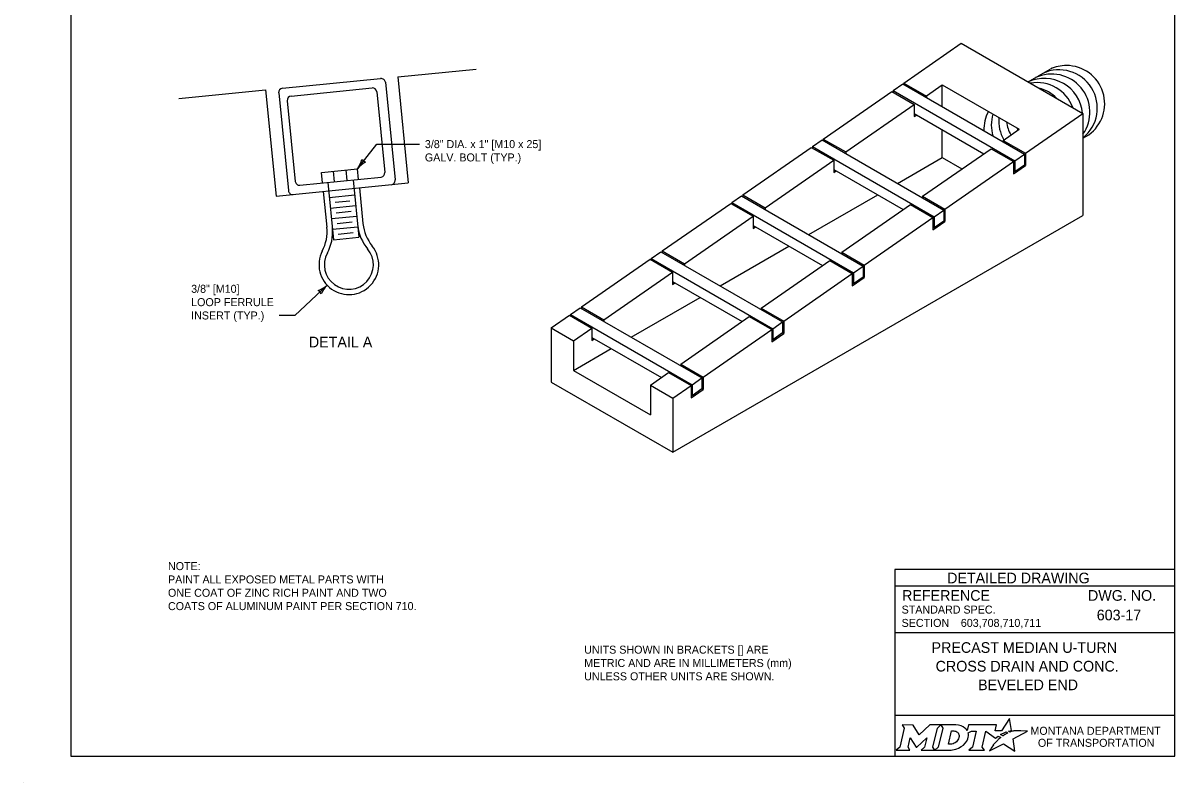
# Model space of a CAD drawing. Extents: x 49991.4 to 50021, y 49987.6 to 50011.4.
# Drawn here: x 49999.98 to 50008.61, y 49999.86 to 50005.56 of the extents above; entities that cross this region are included whole.
import ezdxf

# ---------------------------------------------------------------- set-up
doc = ezdxf.new("R2010")
doc.units = 0
for name, color, linetype in [('Level 1', 7, 'Continuous'), ('Level 2', 7, 'Continuous'), ('Level 3', 7, 'Continuous')]:
    doc.layers.add(name, color=color, linetype=linetype)

msp = doc.modelspace()

# ---------------------------------------------------------------- linework, layer by layer
at = {"layer": 'Level 1'}
for p, q in [((50006.5822, 50005.1123), (50007.0126, 50005.4112)), ((50007.0126, 50005.4112), (50007.9246, 50004.8846)), ((50002.7863, 50005.1589), (50003.3735, 50005.2173)), ((50007.5144, 50005.1214), (50007.68, 50005.217)), ((50001.9223, 50005.0733), (50002.6583, 50005.1461)), ((50002.7863, 50005.1589), (50002.8654, 50004.3629)), ((50001.1447, 50004.9957), (50001.7943, 50005.0605)), ((50001.7943, 50005.0605), (50001.8735, 50004.2637)), ((50001.8935, 50005.0381), (50001.9663, 50004.3052)), ((50001.9863, 50005.0149), (50002.5943, 50005.0757)), ((50002.6295, 50005.0469), (50002.6895, 50004.4421)), ((50002.6935, 50005.1181), (50002.7662, 50004.3854)), ((50005.9776, 50004.6924), (50006.492, 50005.0497)), ((50006.492, 50005.0497), (50006.66, 50004.9527)), ((50006.5008, 50005.0557), (50006.5734, 50005.1062)), ((50006.5008, 50005.0557), (50007.4128, 50004.5292)), ((50006.5008, 50005.0557), (50006.5008, 50005.0446)), ((50006.5734, 50005.1062), (50007.4854, 50004.5796)), ((50006.5822, 50005.1123), (50006.7502, 50005.0152)), ((50006.5822, 50005.1123), (50006.5822, 50005.1011)), ((50006.7502, 50005.0153), (50006.8699, 50005.0984)), ((50006.8699, 50005.0984), (50007.4459, 50004.7658)), ((50006.8699, 50004.935), (50006.8699, 50005.0984)), ((50001.9575, 50004.9797), (50002.0175, 50004.375)), ((50006.1456, 50004.5954), (50006.66, 50004.9527)), ((50006.66, 50004.9527), (50006.66, 50004.861)), ((50006.7502, 50005.0152), (50006.7502, 50005.0041)), ((50006.66, 50004.8838), (50007.1819, 50004.5825)), ((50006.66, 50004.861), (50006.6779, 50004.8734)), ((50007.4942, 50004.5857), (50007.9246, 50004.8846)), ((50007.9246, 50004.8846), (50007.9246, 50004.1182)), ((50005.9776, 50004.6924), (50006.1456, 50004.5955)), ((50005.9776, 50004.6924), (50005.9776, 50004.6813)), ((50006.8699, 50004.5532), (50006.8699, 50004.7626)), ((50007.3262, 50004.6827), (50007.4459, 50004.7658)), ((50007.9246, 50004.6991), (50007.9675, 50004.7238)), ((50005.3731, 50004.2727), (50005.8876, 50004.63)), ((50005.8876, 50004.63), (50006.0555, 50004.5329)), ((50005.8962, 50004.636), (50005.9688, 50004.6864)), ((50005.8962, 50004.636), (50006.8082, 50004.1094)), ((50005.8962, 50004.636), (50005.8962, 50004.625)), ((50005.9688, 50004.6864), (50006.8808, 50004.1599)), ((50006.7216, 50004.2629), (50007.236, 50004.6201)), ((50007.236, 50004.6201), (50007.404, 50004.5232)), ((50007.3262, 50004.6827), (50007.4942, 50004.5857)), ((50007.3262, 50004.6827), (50007.3262, 50004.6715)), ((50005.5411, 50004.1756), (50006.0555, 50004.5329)), ((50006.0555, 50004.5329), (50006.0555, 50004.4412)), ((50006.1456, 50004.5955), (50006.1456, 50004.5843)), ((50006.5348, 50004.3596), (50006.8699, 50004.5532)), ((50006.8699, 50004.5532), (50007.0171, 50004.4681)), ((50006.8896, 50004.166), (50007.404, 50004.5232)), ((50007.404, 50004.5232), (50007.404, 50004.4315)), ((50007.4128, 50004.5292), (50007.4854, 50004.5796)), ((50007.4128, 50004.5292), (50007.4128, 50004.4492)), ((50007.4854, 50004.5796), (50007.4854, 50004.4996)), ((50007.4942, 50004.5857), (50007.4942, 50004.494)), ((50002.214, 50004.4426), (50002.4847, 50004.4697)), ((50002.222, 50004.363), (50002.214, 50004.4426)), ((50002.3016, 50004.4514), (50002.3095, 50004.3718)), ((50002.397, 50004.4609), (50002.405, 50004.3813)), ((50002.4927, 50004.3901), (50002.4847, 50004.4697)), ((50006.0555, 50004.464), (50006.5774, 50004.1628)), ((50006.0555, 50004.4412), (50006.0734, 50004.4537)), ((50007.404, 50004.4315), (50007.4942, 50004.494)), ((50007.404, 50004.4543), (50007.4128, 50004.4492)), ((50007.4128, 50004.4492), (50007.4854, 50004.4996)), ((50007.4854, 50004.4996), (50007.4942, 50004.494)), ((50001.8735, 50004.2637), (50002.8654, 50004.3629)), ((50002.0527, 50004.3461), (50002.6615, 50004.407)), ((50002.2617, 50004.367), (50002.3047, 50003.9362)), ((50002.4528, 50004.3861), (50002.4958, 50003.9552)), ((50002.2283, 50004.2992), (50002.2551, 50004.0313)), ((50002.2729, 50004.2546), (50002.464, 50004.2736)), ((50002.499, 50004.3263), (50002.5258, 50004.0581)), ((50005.2916, 50004.2162), (50005.3643, 50004.2666)), ((50005.3643, 50004.2666), (50006.2763, 50003.7401)), ((50005.3731, 50004.2727), (50005.5411, 50004.1756)), ((50005.3731, 50004.2727), (50005.3731, 50004.2615)), ((50005.8689, 50003.9753), (50006.3855, 50004.2735)), ((50006.7216, 50004.2629), (50006.8896, 50004.166)), ((50006.7216, 50004.2629), (50006.7216, 50004.2518)), ((50002.2809, 50004.175), (50002.472, 50004.194)), ((50002.3167, 50004.2187), (50002.4282, 50004.2298)), ((50004.7685, 50003.8528), (50005.283, 50004.2101)), ((50005.283, 50004.2101), (50005.451, 50004.1132)), ((50005.2916, 50004.2162), (50006.2036, 50003.6896)), ((50005.2916, 50004.2162), (50005.2916, 50004.2051)), ((50005.5411, 50004.1756), (50005.5411, 50004.1645)), ((50006.1171, 50003.8432), (50006.6315, 50004.2004)), ((50006.6315, 50004.2004), (50006.7995, 50004.1033)), ((50002.2888, 50004.0954), (50002.4799, 50004.1144)), ((50002.3247, 50004.1391), (50002.4362, 50004.1502)), ((50004.8493, 50002.3427), (50007.9246, 50004.1182)), ((50004.9365, 50003.7558), (50005.4511, 50004.1131)), ((50005.451, 50004.1132), (50005.451, 50004.0214)), ((50006.2851, 50003.7461), (50006.7995, 50004.1033)), ((50006.7995, 50004.1033), (50006.7995, 50004.0117)), ((50006.8082, 50004.1094), (50006.8808, 50004.1599)), ((50006.8082, 50004.1094), (50006.8082, 50004.0294)), ((50006.8808, 50004.1599), (50006.8808, 50004.0799)), ((50006.8896, 50004.166), (50006.8896, 50004.0742)), ((50002.2968, 50004.0158), (50002.4879, 50004.0348)), ((50002.3326, 50004.0595), (50002.4442, 50004.0706)), ((50005.451, 50004.0442), (50005.9728, 50003.743)), ((50005.451, 50004.0214), (50005.4689, 50004.0339)), ((50006.7995, 50004.0117), (50006.8896, 50004.0742)), ((50006.7995, 50004.0345), (50006.8082, 50004.0294)), ((50006.8082, 50004.0294), (50006.8808, 50004.0799)), ((50006.8808, 50004.0799), (50006.8896, 50004.0742)), ((50002.3047, 50003.9362), (50002.4958, 50003.9552)), ((50002.3406, 50003.9799), (50002.4521, 50003.991)), ((50004.6872, 50003.7964), (50004.7598, 50003.8468)), ((50004.7598, 50003.8468), (50005.6718, 50003.3203)), ((50004.7685, 50003.8528), (50004.9365, 50003.7559)), ((50004.7685, 50003.8528), (50004.7685, 50003.8418)), ((50005.2032, 50003.5908), (50005.7197, 50003.8891)), ((50006.1171, 50003.8432), (50006.2851, 50003.7461)), ((50006.1171, 50003.8432), (50006.1171, 50003.832)), ((50004.164, 50003.4331), (50004.6784, 50003.7904)), ((50004.6784, 50003.7904), (50004.8464, 50003.6933)), ((50004.6872, 50003.7964), (50005.5992, 50003.2698)), ((50004.6872, 50003.7964), (50004.6872, 50003.7853)), ((50004.9365, 50003.7559), (50004.9365, 50003.7448)), ((50005.5125, 50003.4233), (50006.027, 50003.7806)), ((50006.027, 50003.7806), (50006.195, 50003.6836)), ((50006.2851, 50003.7461), (50006.2851, 50003.6544)), ((50004.332, 50003.336), (50004.8465, 50003.6933)), ((50004.8464, 50003.6933), (50004.8464, 50003.6016)), ((50005.6805, 50003.3264), (50006.195, 50003.6836)), ((50006.195, 50003.6836), (50006.195, 50003.5919)), ((50006.195, 50003.5919), (50006.2851, 50003.6544)), ((50006.2036, 50003.6896), (50006.2763, 50003.7401)), ((50006.2036, 50003.6896), (50006.2036, 50003.6096)), ((50006.2036, 50003.6096), (50006.2763, 50003.6601)), ((50006.2763, 50003.7401), (50006.2763, 50003.6601)), ((50006.2763, 50003.6601), (50006.2851, 50003.6544)), ((50004.8464, 50003.6244), (50005.3683, 50003.3232)), ((50004.8464, 50003.6016), (50004.8644, 50003.614)), ((50006.195, 50003.6147), (50006.2036, 50003.6096)), ((50004.5373, 50003.2064), (50005.0539, 50003.5046)), ((50004.0826, 50003.3766), (50004.1552, 50003.427)), ((50004.1552, 50003.427), (50005.0672, 50002.9004)), ((50004.164, 50003.4331), (50004.332, 50003.336)), ((50004.164, 50003.4331), (50004.164, 50003.4219)), ((50005.5125, 50003.4233), (50005.6805, 50003.3264)), ((50005.5125, 50003.4233), (50005.5125, 50003.4123)), ((50003.9374, 50003.2757), (50004.0739, 50003.3705)), ((50004.0739, 50003.3705), (50004.2419, 50003.2736)), ((50004.0826, 50003.3766), (50004.9946, 50002.85)), ((50004.0826, 50003.3766), (50004.0826, 50003.3655)), ((50004.332, 50003.336), (50004.332, 50003.3249)), ((50004.908, 50003.0035), (50005.4224, 50003.3608)), ((50005.4224, 50003.3608), (50005.5904, 50003.2638)), ((50005.5992, 50003.2698), (50005.6718, 50003.3203)), ((50005.6718, 50003.3203), (50005.6718, 50003.2403)), ((50005.6805, 50003.3264), (50005.6805, 50003.2346)), ((50003.9374, 50003.2757), (50003.9374, 50002.8692)), ((50003.9374, 50003.2757), (50004.1054, 50003.1788)), ((50004.1054, 50003.1788), (50004.2419, 50003.2736)), ((50004.2419, 50003.2736), (50004.2419, 50003.1818)), ((50005.076, 50002.9065), (50005.5904, 50003.2638)), ((50005.5904, 50003.2638), (50005.5904, 50003.1721)), ((50005.5904, 50003.1721), (50005.6805, 50003.2346)), ((50005.5992, 50003.2698), (50005.5992, 50003.1898)), ((50005.5992, 50003.1898), (50005.6718, 50003.2403)), ((50005.6718, 50003.2403), (50005.6805, 50003.2346)), ((50004.1054, 50003.1788), (50004.1054, 50002.9571)), ((50004.2419, 50003.2046), (50004.7637, 50002.9033)), ((50004.2419, 50003.1818), (50004.2598, 50003.1943)), ((50005.5904, 50003.1948), (50005.5992, 50003.1898)), ((50004.1054, 50002.9571), (50004.3879, 50003.1203)), ((50004.908, 50003.0035), (50005.076, 50002.9065)), ((50004.908, 50003.0035), (50004.908, 50002.9923)), ((50004.1054, 50002.9571), (50004.6814, 50002.6244)), ((50004.6814, 50002.8461), (50004.8179, 50002.941)), ((50004.8179, 50002.941), (50004.9859, 50002.844)), ((50004.9946, 50002.85), (50005.0672, 50002.9004)), ((50005.0672, 50002.9004), (50005.0672, 50002.8204)), ((50005.076, 50002.9065), (50005.076, 50002.8148)), ((50003.9374, 50002.8692), (50004.8493, 50002.3427)), ((50004.6814, 50002.8461), (50004.6814, 50002.6244)), ((50004.6814, 50002.8461), (50004.8493, 50002.7492)), ((50004.8493, 50002.7492), (50004.9859, 50002.844)), ((50004.9859, 50002.844), (50004.9859, 50002.7523)), ((50004.9859, 50002.7523), (50005.076, 50002.8148)), ((50004.9946, 50002.85), (50004.9946, 50002.77)), ((50004.9946, 50002.77), (50005.0672, 50002.8204)), ((50005.0672, 50002.8204), (50005.076, 50002.8148)), ((50004.8493, 50002.7492), (50004.8493, 50002.3427)), ((50004.9859, 50002.7751), (50004.9946, 50002.77)), ((49999.9766, 49999.8624), (49999.9766, 49999.8624))]:
    msp.add_line(p, q, dxfattribs=at)
msp.add_lwpolyline([(50008.6146, 50011.2628), (50000.3356, 50011.2628), (50000.3356, 50000.0624), (50008.6146, 50000.0624)], close=True, dxfattribs=at)
for centre, radius, start, end in [((50007.7457, 50004.9253), 0.2866, 308.61517, 115.02076), ((50007.8012, 50004.9573), 0.2866, 90, 115.0077), ((50007.8012, 50004.9573), 0.2866, 305.47033, 90), ((50002.6619, 50005.1145), 0.0318, 6.49935, 96.49935), ((50007.6349, 50004.8613), 0.2866, 5.16764, 114.82672), ((50007.6903, 50004.8933), 0.2866, 324.83171, 114.99908), ((50001.9255, 50005.0413), 0.0322, 95.71059, 185.71059), ((50002.5975, 50005.0437), 0.0322, 5.71059, 95.71059), ((50007.5794, 50004.8293), 0.2866, 20.2966, 99.69807), ((50007.524, 50004.7973), 0.2866, 44.31473, 75.67994), ((50001.9895, 50004.9829), 0.0322, 95.71059, 185.71059), ((50007.4686, 50004.7653), 0.2866, 152.17102, 182.11216), ((50007.524, 50004.7973), 0.2866, 163.37199, 196.46639), ((50007.5794, 50004.8293), 0.2866, 175.12903, 209.95947), ((50007.6349, 50004.8613), 0.2866, 188.17367, 208.891), ((50007.6903, 50004.8933), 0.2866, 204.23698, 207.82048), ((50002.6579, 50004.4385), 0.0317, 276.41991, 6.41991), ((50002.0496, 50004.3782), 0.0322, 185.61323, 275.61323), ((50002.7345, 50004.3819), 0.0319, 276.23179, 6.23179), ((50001.9983, 50004.3085), 0.0322, 185.90037, 275.90037), ((50001.9367, 50003.9994), 0.32, 332.65107, 5.7128), ((50001.9777, 50003.9913), 0.32, 331.33979, 5.71115), ((50002.8056, 50004.0739), 0.32, 185.70908, 220.06575), ((50002.8443, 50004.0899), 0.32, 185.7047, 218.73449), ((50002.4199, 50003.7495), 0.224, 152.65107, 38.73449), ((50002.4199, 50003.7495), 0.184, 151.33859, 40.06575)]:
    msp.add_arc(centre, radius, start, end, dxfattribs=at)
at = {"layer": 'Level 2'}
for p, q in [((50008.6146, 50001.4624), (50006.5146, 50001.4624)), ((50006.5146, 50001.4624), (50006.5146, 50000.0624)), ((50008.6146, 50001.3374), (50006.5146, 50001.3374)), ((50008.2507, 50001.1223), (50008.2507, 50001.1223)), ((50008.6146, 50000.9874), (50006.5146, 50000.9874)), ((50007.0089, 50001.0629), (50007.0089, 50001.0629)), ((50007.5646, 50000.7383), (50007.5646, 50000.7383)), ((50008.6146, 50000.3693), (50006.5146, 50000.3693))]:
    msp.add_line(p, q, dxfattribs=at)
for points in [[(50006.5701, 50000.2974), (50006.5842, 50000.274), (50006.5507, 50000.1307), (50006.525, 50000.1082), (50006.6266, 50000.1082), (50006.6131, 50000.131), (50006.6293, 50000.2011), (50006.673, 50000.1321), (50006.6783, 50000.1321), (50006.7534, 50000.2016), (50006.737, 50000.1305), (50006.7123, 50000.1085), (50006.8139, 50000.1085), (50006.8001, 50000.1318), (50006.8333, 50000.2742)], [(50006.8333, 50000.2742), (50006.8586, 50000.2974), (50006.7762, 50000.2974), (50006.6966, 50000.2244), (50006.6521, 50000.2971), (50006.5701, 50000.2974)], [(50006.9722, 50000.2974), (50006.8586, 50000.2974), (50006.8733, 50000.2745), (50006.8394, 50000.1307), (50006.8139, 50000.1085), (50006.9245, 50000.1085)], [(50007.3771, 50000.2447), (50007.3668, 50000.2503), (50007.3784, 50000.2531), (50007.39, 50000.2551), (50007.3726, 50000.3452), (50007.3131, 50000.2539), (50007.2658, 50000.2532), (50007.2761, 50000.2973), (50007.0669, 50000.2974), (50007.0568, 50000.2549), (50007.051, 50000.2632)], [(50006.9962, 50000.2107), (50006.995, 50000.2026), (50006.9918, 50000.1933), (50006.9876, 50000.1851), (50006.982, 50000.1776), (50006.9755, 50000.1707), (50006.9676, 50000.1644), (50006.9593, 50000.1597), (50006.9502, 50000.1558), (50006.9411, 50000.1535), (50006.9319, 50000.1526), (50006.916, 50000.1526), (50006.9396, 50000.2526), (50006.9556, 50000.2526), (50006.9632, 50000.252), (50006.9708, 50000.2501), (50006.9774, 50000.2471), (50006.9835, 50000.2429), (50006.9883, 50000.2379), (50006.992, 50000.2319), (50006.9947, 50000.2257), (50006.9963, 50000.2183), (50006.9963, 50000.2153), (50006.9962, 50000.2107)], [(50007.0636, 50000.2383), (50007.0882, 50000.2514), (50007.1251, 50000.2514), (50007.0965, 50000.1309), (50007.069, 50000.1082), (50007.1852, 50000.1082), (50007.1682, 50000.1311), (50007.1964, 50000.2513), (50007.2677, 50000.1996), (50007.2888, 50000.2147), (50007.3085, 50000.2038)], [(50007.2527, 50000.1479), (50007.2374, 50000.1235), (50007.2327, 50000.116), (50007.2269, 50000.1074), (50007.2246, 50000.1031), (50007.3299, 50000.1562), (50007.4138, 50000.1011), (50007.4007, 50000.1938), (50007.5076, 50000.2522), (50007.4583, 50000.253), (50007.4282, 50000.2534), (50007.4074, 50000.2537), (50007.4006, 50000.2522), (50007.3957, 50000.251), (50007.3873, 50000.2487), (50007.3771, 50000.2447)], [(50007.3267, 50000.2171), (50007.3243, 50000.2154), (50007.306, 50000.225), (50007.3163, 50000.2307), (50007.3204, 50000.2329), (50007.329, 50000.2369), (50007.3347, 50000.2395), (50007.3426, 50000.2425), (50007.3499, 50000.2452), (50007.3617, 50000.2378), (50007.3577, 50000.2357), (50007.3531, 50000.2332), (50007.3489, 50000.231), (50007.3439, 50000.2281), (50007.342, 50000.227), (50007.3393, 50000.2254), (50007.3368, 50000.224), (50007.3345, 50000.2224), (50007.3319, 50000.2206), (50007.3292, 50000.2188), (50007.3267, 50000.2171)], [(50006.9702, 50000.1158), (50006.9786, 50000.1184), (50006.9916, 50000.1238), (50007.012, 50000.1348)], [(50007.2666, 50000.164), (50007.2666, 50000.164)]]:
    msp.add_lwpolyline(points, dxfattribs=at)
for centre, radius, start, end in [((50006.9953, 50000.219), 0.0709, 339.53292, 15.85821), ((50006.9513, 50000.2363), 0.1183, 300.91025, 339.13831)]:
    msp.add_arc(centre, radius, start, end, dxfattribs=at)
for centre, major_axis, ratio, start_param, end_param in [((50006.9701, 50000.25), (0.0834, -0.0037), 0.568097, 0.61298, 1.570796), ((50007.0257, 50000.2573), (0.0361, -0.0295), 0.469099, 1.225588, 1.570796), ((50007.2974, 50000.1941), (-0.0112, -0.0097), 0.021651, 3.157348, 6.283185), ((50006.9248, 50000.2568), (0, 0.1484), 0.987302, 3.139398, 3.456847), ((50007.2597, 50000.1559), (-0.00694, -0.00806), 0.008222, 0, 3.137361), ((50007.2764, 50000.1742), (-0.0098, -0.0102), 0.016458, 3.141593, 6.279097)]:
    msp.add_ellipse(centre, major_axis=major_axis, ratio=ratio, start_param=start_param, end_param=end_param, dxfattribs=at)
at = {"layer": 'Level 3'}
for p, q in [((50002.4847, 50004.4697), (50002.6287, 50004.6544)), ((50002.6287, 50004.6544), (50002.9499, 50004.6544)), ((50002.2564, 50003.5964), (50002.0137, 50003.369)), ((50002.0137, 50003.369), (50001.8967, 50003.369))]:
    msp.add_line(p, q, dxfattribs=at)
for centre, radius, start, end in [((50002.2941, 50004.6037), 0.233, 324.88581, 344.13566), ((50002.6543, 50004.3259), 0.2223, 119.51451, 139.69802), ((50002.5635, 50004.5708), 0.0548, 214.19732, 249.91968), ((50002.1112, 50003.7648), 0.2223, 290.59191, 310.77541), ((50002.4239, 50003.4345), 0.233, 135.96321, 155.21306), ((50002.1628, 50003.5087), 0.0548, 25.27471, 60.99708)]:
    msp.add_arc(centre, radius, start, end, dxfattribs=at)

# ---------------------------------------------------------------- texts
at = {"layer": 'Level 2'}
for s, height, p in [('3/8" DIA. x 1" [M10 x 25]', 0.06, (50002.9899, 50004.6244)), ('GALV. BOLT (TYP.)', 0.06, (50002.9899, 50004.5244)), ('3/8" [M10] ', 0.06, (50001.2373, 50003.539)), ('LOOP FERRULE', 0.06, (50001.2373, 50003.439)), ('INSERT (TYP.)', 0.06, (50001.2373, 50003.339)), ('DETAIL A', 0.08, (50002.12, 50003.1297)), ('NOTE:', 0.06, (50001.0636, 50001.459)), ('PAINT ALL EXPOSED METAL PARTS WITH', 0.06, (50001.0636, 50001.359)), ('DETAILED DRAWING', 0.0799, (50006.9063, 50001.3599)), ('ONE COAT OF ZINC RICH PAINT AND TWO', 0.06, (50001.0636, 50001.259)), ('REFERENCE', 0.08, (50006.5682, 50001.229)), ('DWG. NO.', 0.08, (50007.9624, 50001.229)), ('COATS OF ALUMINUM PAINT PER SECTION 710.', 0.06, (50001.0636, 50001.159)), ('STANDARD SPEC.', 0.06, (50006.5649, 50001.133)), ('603-17', 0.08, (50008.0281, 50001.0823)), ('SECTION', 0.06, (50006.5649, 50001.033)), ('603,708,710,711', 0.06, (50007.0089, 50001.0329)), ('UNITS SHOWN IN BRACKETS [] ARE', 0.06, (50004.1847, 50000.8324)), ('PRECAST MEDIAN U-TURN', 0.08, (50006.7893, 50000.8383)), ('METRIC AND ARE IN MILLIMETERS (mm)', 0.06, (50004.1847, 50000.7324)), ('CROSS DRAIN AND CONC.', 0.08, (50006.8199, 50000.6983)), ('UNLESS OTHER UNITS ARE SHOWN.', 0.06, (50004.1847, 50000.6324)), ('BEVELED END', 0.08, (50007.1384, 50000.5583)), ('MONTANA DEPARTMENT', 0.06, (50007.5308, 50000.2236)), ('OF TRANSPORTATION', 0.06, (50007.587, 50000.1336))]:
    msp.add_text(s, height=height, dxfattribs=at).set_placement(p)

doc.saveas('drawing.dxf')
